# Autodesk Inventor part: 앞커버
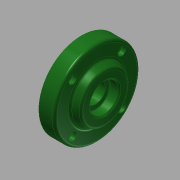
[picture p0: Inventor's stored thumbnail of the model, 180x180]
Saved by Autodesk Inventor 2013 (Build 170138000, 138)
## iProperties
Company: 한국ATC센터
Created: 2015-12
Part Number: 앞커버
Document SubType Name: Modeling
Designer: 앞커버
Density: 2.71 g/cm^3
Mass: 114.339 g
Surface Area: 117.889 cm^2
Volume: 42.1916 cm^3
Material: 알루미늄-6061
Author: mdu
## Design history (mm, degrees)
sketch "스케치1"
  geometry: L1 (-11.5, 0)-(11.5, 0); L2 (11.5, 0)-(11.5, 22.5); L3 (11.5, 22.5)-(6.5, 22.5); L4 (6.5, 22.5)-(6.5, 32.5); L5 (6.5, 32.5)-(-5.5, 32.5); L6 (-5.5, 32.5)-(-5.5, 21); L7 (-5.5, 21)-(-11.5, 18.202); L8 (-11.5, 18.202)-(-11.5, 0); 2 further points
  constraints: 16 end point, 3 parallel, 3 perpendicular, 1 coincident, 1 horizontal, 1 midpoint
  dimensions: "d0" = 23 distance of L1.start L1.end; "d1" = 65 diameter of L5 L1; "d2" = 45 diameter of L3 L1; "d3" = 42 diameter of L6.end L1; "d4" = 115 deg angle of L7 L6; "d5" = 12 distance of L4.end L5.end; "d6" = 5 distance of L2.end L3.end
revolve "회전1" sketch "스케치1" stored, may be unused: angle "d7" = 90 deg
sketch "스케치2"
  geometry: L1 (0, 0)-(32.5, 0); L2 (0, 0)-(18.738, 18.738); 1 further point
  constraints: 4 end point, 1 horizontal, 1 horizontal alignment, 1 other
  dimensions: "d8" = 45 deg angle of L1 L2; "d9" = 26.5 distance of L1.start L2.end
hole "구멍1" sketch "스케치2" at (18.738, 18.738) diameter "d10" = 3.4; stored, may be unused: countersink angle "d14" = 90 deg, drill point angle "d16" = 118 deg; dims "d11" = 6, "d12" = 6, "d13" = 3.3, "d15" = 8
fillet "모깎기1" dims "d20" = 2
hole "구멍2" diameter "d23" = 15; stored, may be unused: countersink angle "d27" = 90 deg, drill point angle "d29" = 118 deg; dims "d21" = 10, "d22" = 10, "d24" = 6, "d25" = 32, "d26" = 10, "d28" = 8
hole "구멍3" diameter "d32" = 22; stored, may be unused: countersink angle "d36" = 90 deg, drill point angle "d38" = 0 deg; dims "d30" = 10, "d31" = 10, "d33" = 6, "d34" = 32, "d35" = 10, "d37" = 7.3
chamfer "모따기1" distance "d39" = 1; stored, may be unused: second distance "d40" = 2, angle "d41" = 45 deg
fillet "모깎기2" dims "d42" = 0.3
node "작업 평면1"
sketch "스케치3"
  geometry: 2 further points
  constraints: 1 coincident, 1 other
feature "엠보싱1" sketch "스케치3" dims "d44" = 0.3, "d45" = 0
fillet "모깎기3" dims "d46" = 0.2
fillet "모깎기4" dims "d47" = 0.1
node "솔리드1"
pattern_circular "원형 패턴1" dims angle "d18" = 360 deg
